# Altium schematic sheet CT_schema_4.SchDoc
size 287 x 169 mm
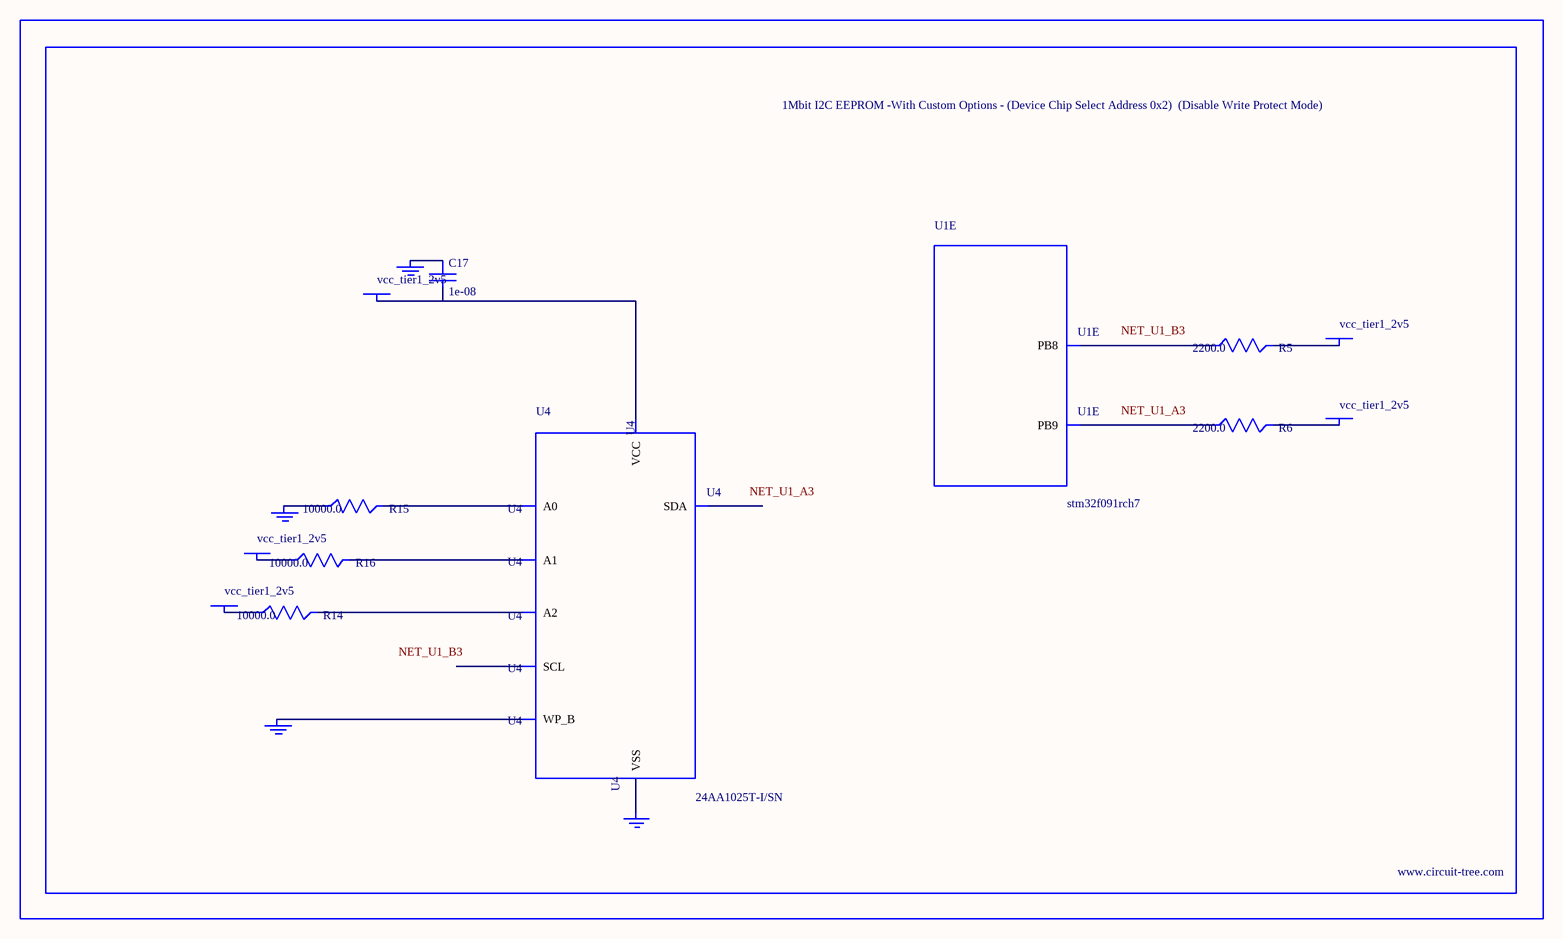
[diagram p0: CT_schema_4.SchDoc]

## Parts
BORDER3  (no value)
C17  1e-08  [C0402]
GND_INSTANCE_3_0  (no value)
GND_INSTANCE_3_1  (no value)
GND_INSTANCE_3_2  (no value)
GND_INSTANCE_3_3  (no value)
POWER_INSTANCE_3_0  vcc_tier1_2v5
POWER_INSTANCE_3_1  vcc_tier1_2v5
POWER_INSTANCE_3_2  vcc_tier1_2v5
POWER_INSTANCE_3_3  vcc_tier1_2v5
POWER_INSTANCE_3_4  vcc_tier1_2v5
R5  2200.0  [R0603]
R6  2200.0  [R0603]
R14  10000.0  [R0603]
R15  10000.0  [R0603]
R16  10000.0  [R0603]
U1  stm32f091rch7  [UFBGA64]  (part E of 6)
U4  24AA1025T-I/SN  [SOIC-8]

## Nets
NetC17_1: C17.1 GND_INSTANCE_3_2.0(GND)
NetC17_2: C17.2 POWER_INSTANCE_3_2.0(PWR) U4.8(VCC)
NetGND_INSTANCE_3_0_0: GND_INSTANCE_3_0.0(GND) R15.1
NetGND_INSTANCE_3_1_0: GND_INSTANCE_3_1.0(GND) U4.7(WP_B)
NetGND_INSTANCE_3_3_0: GND_INSTANCE_3_3.0(GND) U4.4(VSS)
NetPOWER_INSTANCE_3_0_0: POWER_INSTANCE_3_0.0(PWR) R16.1
NetPOWER_INSTANCE_3_1_0: POWER_INSTANCE_3_1.0(PWR) R14.1
NetPOWER_INSTANCE_3_3_0: POWER_INSTANCE_3_3.0(PWR) R5.2
NetPOWER_INSTANCE_3_4_0: POWER_INSTANCE_3_4.0(PWR) R6.2
NetR5_1: R5.1 U1.B3(PB8)
NetR6_1: R6.1 U1.A3(PB9)
NetR14_2: R14.2 U4.3(A2)
NetR15_2: R15.2 U4.1(A0)
NetR16_2: R16.2 U4.2(A1)

Not connected (* = marked no-connect by the designer): U4 5(SDA) 6(SCL)

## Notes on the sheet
- Labels drawn without touching a wire or pin: NET_U1_A3, NET_U1_B3

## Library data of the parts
BORDER3 = BORDER_PAGE3
C17 = C0402C103K3RAC
GND_INSTANCE_3_0-GND_INSTANCE_3_3 = GND
POWER_INSTANCE_3_0-POWER_INSTANCE_3_4 = PWR
R5 R6 = RC0603JR-072K2L
R14-R16 = RC0603JR-0710KL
